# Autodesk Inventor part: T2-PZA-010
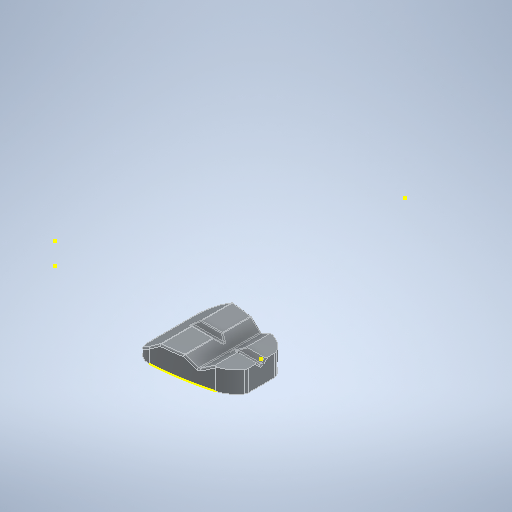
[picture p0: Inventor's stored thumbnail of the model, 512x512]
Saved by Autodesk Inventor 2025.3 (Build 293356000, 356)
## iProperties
Created: 2026-10
Part Number: T2-PZA-010
Material: Genérico
Description: Soporte de punta flexible
Document SubType Name: Modeling
Designer: Luis MuÃ±oz
Density: 1 g/cm^3
Appearance: Valor por defecto
Project: TESIS 2 - Plataforma mecatrÃ³nica preventiva desacoplada
Sending System: ONSHAPE BY PTC INC, 1.194
Preprocessor: ST-DEVELOPER v20
Material_Fabricacion: PLA
Title: Soporte de punta flexible
Revision Number: 00
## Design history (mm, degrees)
feature "Tip_Support"
sketch "Boceto1"
  geometry: A1 r 92.826 centre (0, -71.969) between (15.78, 19.506) and (8.727, 20.446) reference; A2 r 92.826 centre (0, -71.969) between (8.727, 20.446) and (5.285, 20.707) reference; A3 r 92.826 centre (0, -71.969) between (24.757, 17.495) and (5.285, 20.707) reference; A4 r 92.826 centre (0, -71.969) between (24.757, 17.495) and (20.626, 18.537) reference; A5 r 92.826 centre (0, -71.969) between (19.591, 18.767) and (15.78, 19.506) reference; 1 further point
  constraints: 1 other
  node "Contorno proyectado1"
sketch "Boceto2"
  geometry: 1 further point
sketch "Boceto3"
  geometry: L1 (15.952, 9.565)-(15.952, 19.014) reference; L2 (30.75, 12.289)-(30.75, 3.426) reference; L3 (0, 0)-(0, 15.715) reference; C1 r 1.025 at (21.75, 7.858) reference; C2 r 1.025 at (11.75, 11.358) reference; C3 r 1.025 at (11.75, 4.358) reference; A1 r 10 centre (22.09, 7.858) between (24.757, -1.78) and (30.415, 2.318) reference; A2 r 2 centre (28.75, 3.426) between (30.415, 2.318) and (30.75, 3.426) reference; A3 r 2 centre (28.75, 12.289) between (30.75, 12.289) and (30.415, 13.397) reference; A4 r 10 centre (22.09, 7.858) between (30.415, 13.397) and (24.757, 17.495) reference; A5 r 92.826 centre (0, -71.969) between (24.757, 17.495) and (5.285, 20.707) reference; A6 r 5 centre (5, 15.715) between (5.285, 20.707) and (0, 15.715) reference; A7 r 5 centre (5, 0) between (0, 0) and (5.285, -4.992) reference; A8 r 92.826 centre (0, 87.684) between (5.285, -4.992) and (24.757, -1.78) reference; 1 further point
extrude "Extrusión1" cut sketch "Boceto3" stored distance "d0" = 10; taper "d1" = 0 deg
sketch "Boceto4"
  geometry: 1 further point
sketch "Boceto5"
  geometry: L1 (-6.139, 7.25)-(-16.523, 7.25) reference; L2 (-14.219, 7.25)-(6.85, 7.25); L3 (6.85, 7.25)-(6.85, 9.582); L4 (6.85, 9.582)-(-14.219, 9.582); L5 (-14.219, 9.582)-(-14.219, 7.25); 2 further points
  constraints: 8 end point, 2 parallel, 1 horizontal, 1 perpendicular, 1 point on line
extrude "Extrusión2" cut sketch "Boceto5" distance "d2" = 29.25; taper "d3" = 0 deg
node "Sólido1"
node "Contorno proyectado2"
